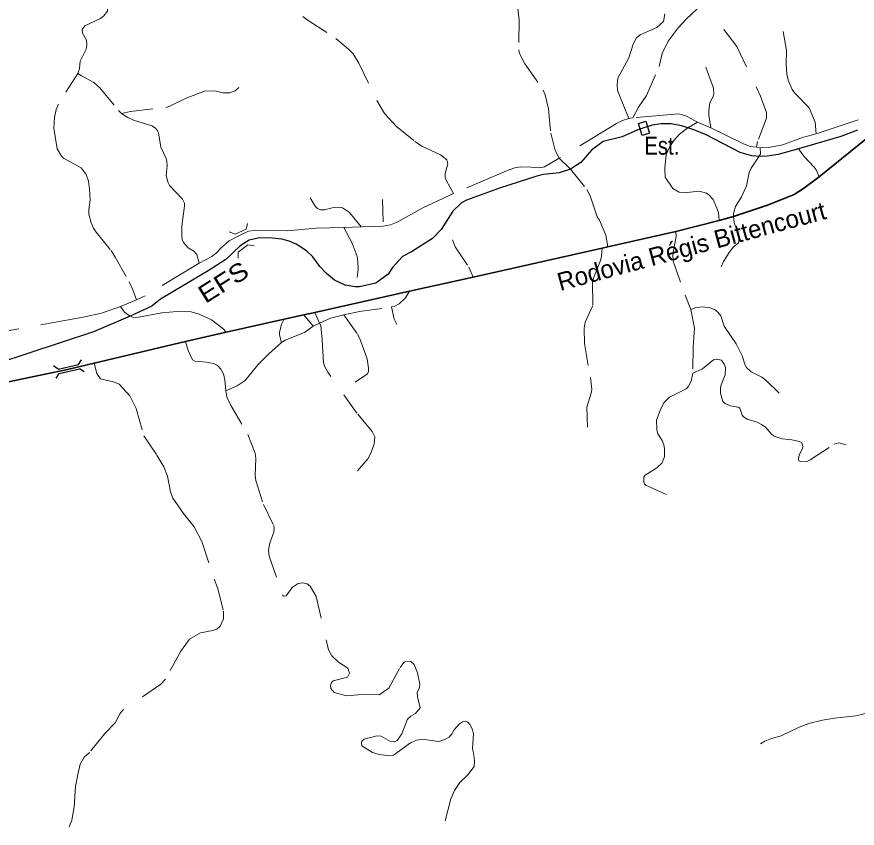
# Model space of a CAD drawing. Extents: x 220.8 to 246.7, y 7287.6 to 7315.8.
# Drawn here: x 239.405 to 243.157, y 7305.147 to 7308.771 of the extents above; entities that cross this region are included whole.
import ezdxf
from ezdxf.enums import TextEntityAlignment as Align

# ---------------------------------------------------------------- set-up
doc = ezdxf.new("R2010")
doc.units = 0
doc.header["$LTSCALE"] = 0.032
for name, pattern in [('DOTTED', [1.5, 0.3, -1.2]), ('LONG_DASHED', [7.5, 6, -1.5]), ('MEDIUM_DASHED', [4.5, 3, -1.5])]:
    doc.linetypes.add(name, pattern=pattern)
for name, color, linetype, lineweight in [('10', 7, 'Continuous', 25), ('11', 7, 'Continuous', 13), ('15', 7, 'Continuous', 25), ('2', 7, 'Continuous', 35), ('28', 7, 'Continuous', 25), ('5', 7, 'LONG_DASHED', 13), ('6', 7, 'MEDIUM_DASHED', 13), ('7', 7, 'DOTTED', 13)]:
    doc.layers.add(name, color=color, linetype=linetype, lineweight=lineweight)
doc.layers.add('61', color=7, linetype='Continuous')

msp = doc.modelspace()

# ---------------------------------------------------------------- linework, layer by layer
at = {"layer": '10'}
for p, q in [((239.5894, 7307.1977), (239.5686, 7307.2113)), ((239.5803, 7307.1573), (239.5937, 7307.1782)), ((239.5937, 7307.1782), (239.6841, 7307.1978)), ((239.7051, 7307.1844), (239.6841, 7307.1978))]:
    msp.add_line(p, q, dxfattribs=at)
msp.add_lwpolyline([(239.5894, 7307.1977), (239.6798, 7307.2174), (239.6934, 7307.2384)], dxfattribs=at)
at = {"layer": '11'}
for points in [[(240.4354, 7307.8477), (240.4286, 7307.8218), (240.3794, 7307.7994), (240.3534, 7307.8101)], [(240.3926, 7307.6931), (240.3936, 7307.7199), (240.4367, 7307.7525), (240.4644, 7307.7477)]]:
    msp.add_lwpolyline(points, dxfattribs=at)
at = {"layer": '15'}
for points in [[(243.1583, 7308.265), (243.0839, 7308.236), (242.8956, 7308.1818), (242.8045, 7308.1556), (242.7549, 7308.1479), (242.7241, 7308.1462), (242.6865, 7308.1497), (242.6344, 7308.1642), (242.4823, 7308.2437), (242.4327, 7308.265), (242.4016, 7308.2747), (242.3721, 7308.2838), (242.3259, 7308.2924), (242.2815, 7308.2924), (242.2422, 7308.2864), (242.1772, 7308.2667), (242.108, 7308.2343), (242.0234, 7308.2137), (241.9713, 7308.1753), (241.9226, 7308.1197), (241.8763, 7308.0903), (241.826, 7308.0736), (241.7568, 7308.0668), (241.726, 7308.0591), (241.5594, 7308.0052), (241.4132, 7307.9514), (241.3902, 7307.9394), (241.3517, 7307.9027), (241.2996, 7307.8206), (241.2611, 7307.7813), (241.1663, 7307.7215), (241.1261, 7307.7002), (241.0817, 7307.6506), (241.0629, 7307.6215), (241.0073, 7307.5814), (240.9355, 7307.5643), (240.915, 7307.5643), (240.8706, 7307.572), (240.8227, 7307.595), (240.7877, 7307.6241), (240.7578, 7307.6557), (240.7262, 7307.6993), (240.6988, 7307.7249), (240.6527, 7307.7548), (240.6211, 7307.7685), (240.5886, 7307.7779), (240.545, 7307.7822), (240.4878, 7307.783), (240.4425, 7307.7736), (240.4014, 7307.748)], [(240.4014, 7307.748), (240.3382, 7307.6873), (240.2587, 7307.6361), (240.0468, 7307.5096), (240.0075, 7307.4788), (239.9108, 7307.4345), (239.7468, 7307.3643), (239.3125, 7307.2206)]]:
    msp.add_lwpolyline(points, dxfattribs=at)
at = {"layer": '2'}
msp.add_lwpolyline([(239.3316, 7307.1323), (239.6303, 7307.1959), (239.7503, 7307.2242), (240.1574, 7307.3206), (240.3398, 7307.3618), (240.5989, 7307.4198), (240.6861, 7307.4393), (240.736, 7307.4505), (241.158, 7307.5449), (241.4416, 7307.6085), (242.0188, 7307.7379), (242.043, 7307.7433), (242.3478, 7307.8117), (242.5412, 7307.8613), (242.6047, 7307.8784), (242.757, 7307.9292), (242.8764, 7307.9777), (242.9171, 7308.004), (242.9873, 7308.0568), (243.1979, 7308.2257)], dxfattribs=at)
at = {"layer": '28'}
msp.add_lwpolyline([(242.2126, 7308.3047), (242.23, 7308.2504), (242.1977, 7308.2401), (242.1803, 7308.2944)], close=True, dxfattribs=at)
at = {"layer": '5'}
for points in [[(242.1368, 7308.3159), (242.0873, 7308.441), (242.0847, 7308.4687), (242.0886, 7308.4965), (242.1376, 7308.5877), (242.1561, 7308.6485), (242.1719, 7308.6776), (242.1878, 7308.6908), (242.2631, 7308.7238), (242.2916, 7308.7506), (242.2984, 7308.7836)], [(243.1608, 7308.311), (242.9743, 7308.2489), (242.9124, 7308.2325), (242.8258, 7308.1983), (242.7695, 7308.1883), (242.7246, 7308.1859), (242.7079, 7308.188), (242.679, 7308.1923), (242.6468, 7308.2054), (242.5037, 7308.2744), (242.4442, 7308.3006), (242.3951, 7308.3273), (242.3611, 7308.3371), (242.1548, 7308.3196), (242.1368, 7308.3159)], [(242.1368, 7308.3159), (242.1086, 7308.308), (242.0824, 7308.2939), (241.827, 7308.1399), (241.7615, 7308.1007), (241.7485, 7308.0977), (241.6529, 7308.1007), (241.6278, 7308.0967), (241.5905, 7308.0836), (241.3538, 7307.981), (241.2173, 7307.9177), (241.1037, 7307.8533), (241.0735, 7307.8412), (241.0404, 7307.8359), (240.9425, 7307.8327), (240.865, 7307.8302), (240.7395, 7307.8261), (240.6138, 7307.815), (240.4649, 7307.8171), (240.4397, 7307.813), (240.3923, 7307.7913), (240.3532, 7307.7708), (240.318, 7307.7406), (240.2949, 7307.7155), (240.2747, 7307.7004), (240.2184, 7307.6698), (239.978, 7307.5243), (239.9393, 7307.5065), (239.8673, 7307.477)], [(239.8673, 7307.477), (239.7828, 7307.4479), (239.7003, 7307.4298), (239.3631, 7307.368), (239.1492, 7307.3307), (239.0324, 7307.308), (238.8563, 7307.302), (238.8201, 7307.296), (238.789, 7307.2829), (238.7155, 7307.2296), (238.6854, 7307.218)], [(239.8673, 7307.477), (239.8857, 7307.4516), (239.9108, 7307.4345), (239.9221, 7307.4295), (239.9399, 7307.4273), (240.0521, 7307.4487), (240.1206, 7307.4552), (240.1827, 7307.453), (240.2192, 7307.443), (240.2734, 7307.418), (240.3241, 7307.3781), (240.3398, 7307.3618)]]:
    msp.add_lwpolyline(points, dxfattribs=at)
at = {"layer": '6'}
for points in [[(240.6812, 7308.7726), (240.7049, 7308.7547), (240.8284, 7308.6742), (240.8859, 7308.6268), (240.906, 7308.6053), (240.9311, 7308.5644), (241.0123, 7308.3977), (241.046, 7308.3389), (241.1006, 7308.2814), (241.1825, 7308.2139), (241.2155, 7308.1909), (241.296, 7308.155), (241.3254, 7308.132), (241.3297, 7308.1148), (241.3175, 7308.0703), (241.3175, 7308.0545), (241.3211, 7308.0415), (241.3538, 7307.981)], [(240.1574, 7307.3206), (240.1693, 7307.2801), (240.1897, 7307.2381), (240.1996, 7307.2325), (240.2496, 7307.2288), (240.283, 7307.222), (240.3009, 7307.2127), (240.3163, 7307.1973), (240.3268, 7307.1763), (240.3342, 7307.1497), (240.3373, 7307.0996), (240.3417, 7307.0737), (240.359, 7307.0373), (240.4362, 7306.9057), (240.4683, 7306.8216), (240.472, 7306.7975), (240.4695, 7306.7216), (240.472, 7306.6993), (240.506, 7306.5924), (240.5517, 7306.4991), (240.5542, 7306.4849), (240.553, 7306.4695), (240.5338, 7306.4213), (240.5289, 7306.3892), (240.5313, 7306.362), (240.5913, 7306.1896), (240.5956, 7306.1834), (240.6068, 7306.1846), (240.6339, 7306.2211), (240.6612, 7306.2397), (240.682, 7306.2426), (240.7006, 7306.2386), (240.7145, 7306.2275), (240.7414, 7306.1822), (240.797, 7305.9431), (240.8118, 7305.9171), (240.8409, 7305.8881), (240.8779, 7305.8646), (240.8841, 7305.8584), (240.8878, 7305.8485)], [(239.7503, 7307.2242), (239.7624, 7307.1773), (239.7779, 7307.1534), (239.8358, 7307.1405), (239.861, 7307.1302), (239.9093, 7307.078), (239.937, 7307.022), (239.9712, 7306.8989), (240.0304, 7306.8126), (240.0607, 7306.761), (240.0775, 7306.7185), (240.0904, 7306.6496), (240.102, 7306.6212), (240.149, 7306.5529), (240.196, 7306.4923), (240.2302, 7306.4266), (240.2856, 7306.2597), (240.3023, 7306.2179), (240.3275, 7306.1161)]]:
    msp.add_lwpolyline(points, dxfattribs=at)
at = {"layer": '7'}
for p, q in [((242.4031, 7308.2757), (242.4016, 7308.2747)), ((241.8759, 7308.0908), (241.8763, 7308.0903)), ((241.0381, 7307.9547), (241.0404, 7307.8359)), ((240.6861, 7307.4393), (240.7283, 7307.3895)), ((240.7564, 7307.403), (240.736, 7307.4505)), ((240.7283, 7307.3895), (240.7564, 7307.403))]:
    msp.add_line(p, q, dxfattribs=at)
for points in [[(242.1548, 7308.3196), (242.1803, 7308.3672), (242.2159, 7308.4198), (242.2723, 7308.5485), (242.2856, 7308.6064), (242.3127, 7308.6623), (242.3574, 7308.7213), (242.393, 7308.7606), (242.469, 7308.8308), (242.5333, 7308.8807), (242.57, 7308.9169), (242.5923, 7308.9499), (242.6099, 7308.9956), (242.6264, 7309.2369), (242.638, 7309.3268), (242.6423, 7309.4108), (242.6604, 7309.5554), (242.6673, 7309.6442), (242.6444, 7309.7329), (242.6269, 7309.8993), (242.6173, 7309.9445)], [(241.7065, 7309.2353), (241.6979, 7309.2171), (241.681, 7309.1595), (241.6666, 7309.1263), (241.629, 7308.9264), (241.6284, 7308.8775), (241.6415, 7308.8092), (241.6478, 7308.7565), (241.6459, 7308.6237), (241.6478, 7308.6105), (241.6735, 7308.5604), (241.7549, 7308.4432), (241.7637, 7308.4225), (241.7781, 7308.3605), (241.7888, 7308.2508), (241.807, 7308.1794), (241.8139, 7308.1612), (241.827, 7308.1399), (241.8763, 7308.0903)], [(239.8314, 7309.2094), (239.8358, 7309.1781), (239.8349, 7309.1382), (239.8036, 7309.0763), (239.8004, 7309.053), (239.8077, 7309.0259), (239.8211, 7308.999), (239.825, 7308.9802), (239.8234, 7308.9525), (239.8141, 7308.9148), (239.809, 7308.8775), (239.8103, 7308.7954), (239.7934, 7308.7753), (239.7777, 7308.7638), (239.7078, 7308.7306), (239.696, 7308.7137), (239.698, 7308.6984), (239.7158, 7308.6665), (239.7177, 7308.6445), (239.7139, 7308.6269), (239.6877, 7308.5723), (239.6849, 7308.5398), (239.6775, 7308.5181)], [(242.5617, 7308.7139), (242.6191, 7308.6382), (242.7254, 7308.4158), (242.7514, 7308.3435), (242.7522, 7308.3184), (242.7122, 7308.2142), (242.7079, 7308.188)], [(242.8268, 7308.7048), (242.8417, 7308.621), (242.8406, 7308.5608), (242.8434, 7308.5147), (242.8489, 7308.4877), (242.8669, 7308.4465), (242.8791, 7308.4303), (242.9421, 7308.3648), (242.9698, 7308.3008), (242.9743, 7308.2489)], [(242.5037, 7308.2744), (242.4945, 7308.3308), (242.4945, 7308.3521), (242.4995, 7308.3864), (242.5125, 7308.4113), (242.5167, 7308.426), (242.5161, 7308.4518), (242.4638, 7308.5918)], [(239.6775, 7308.5181), (239.5907, 7308.3812), (239.5799, 7308.3563), (239.5735, 7308.3218), (239.5706, 7308.2733), (239.5843, 7308.1814), (239.6044, 7308.1485), (239.6137, 7308.1396), (239.6916, 7308.0968), (239.7145, 7308.0665), (239.7248, 7308.0368), (239.7295, 7308.0011), (239.7324, 7307.9535), (239.726, 7307.9091), (239.7267, 7307.89), (239.7366, 7307.851), (239.7471, 7307.8262), (239.7583, 7307.8096), (239.8256, 7307.7266), (239.8435, 7307.6972), (239.906, 7307.5877), (239.9233, 7307.551), (239.9393, 7307.5065)], [(239.6775, 7308.5181), (239.6928, 7308.5066), (239.7479, 7308.4769), (239.7753, 7308.4534), (239.8593, 7308.3522), (239.8728, 7308.3397)], [(239.8728, 7308.3397), (239.9129, 7308.3481), (240.0702, 7308.3659), (240.0915, 7308.3732), (240.1612, 7308.4081), (240.2421, 7308.4387), (240.2889, 7308.4408), (240.3258, 7308.4311), (240.3561, 7308.4307), (240.3799, 7308.4398), (240.3956, 7308.4558)], [(239.8728, 7308.3397), (239.9004, 7308.3209), (239.9258, 7308.3096), (240.0075, 7308.2834), (240.0236, 7308.2728), (240.0333, 7308.2615), (240.0372, 7308.2529), (240.0478, 7308.1879), (240.0709, 7308.1387), (240.0744, 7308.125), (240.0763, 7308.1066), (240.072, 7308.0616), (240.0803, 7308.0292), (240.0865, 7308.0171), (240.144, 7307.9557), (240.153, 7307.9389), (240.1538, 7307.9264), (240.142, 7307.8364), (240.1409, 7307.7926), (240.1436, 7307.7758), (240.1495, 7307.7633), (240.1698, 7307.7394), (240.1956, 7307.7238), (240.2085, 7307.7093), (240.2184, 7307.6698)], [(242.4442, 7308.3006), (242.4016, 7308.2747), (242.3642, 7308.2468), (242.3378, 7308.218), (242.3208, 7308.1915), (242.3043, 7308.1561), (242.2977, 7308.0952), (242.2991, 7308.0551), (242.3335, 7308.0046), (242.3628, 7307.9872), (242.3845, 7307.9843), (242.452, 7307.9914), (242.4846, 7307.9829), (242.495, 7307.9763), (242.5143, 7307.9546), (242.5304, 7307.9164), (242.5379, 7307.897), (242.5412, 7307.8613)], [(242.7246, 7308.1859), (242.725, 7308.1582), (242.7171, 7308.1438), (242.6838, 7308.0942), (242.6754, 7308.0759), (242.6634, 7308.016), (242.6405, 7307.9661), (242.6143, 7307.9236), (242.6051, 7307.8928), (242.6047, 7307.8784), (242.6076, 7307.8516), (242.6188, 7307.8225), (242.628, 7307.7859), (242.6284, 7307.765), (242.6259, 7307.7592), (242.6047, 7307.743), (242.5855, 7307.7184), (242.5606, 7307.6785), (242.5493, 7307.6539)], [(242.8948, 7308.1833), (242.8956, 7308.1818), (242.9193, 7308.1483), (242.9651, 7308.0992), (242.9738, 7308.0872), (242.9873, 7308.0568)], [(241.8763, 7308.0903), (241.9499, 7307.999), (241.965, 7307.9717), (241.9966, 7307.8775), (242.0067, 7307.8631), (242.034, 7307.7961), (242.043, 7307.7433)], [(240.7147, 7307.963), (240.7375, 7307.9245), (240.7477, 7307.9148), (240.7607, 7307.9092), (240.7783, 7307.9088), (240.8126, 7307.9176), (240.8516, 7307.9194), (240.8595, 7307.9171), (240.8901, 7307.8967), (240.9425, 7307.8327)], [(240.9249, 7307.6058), (240.9281, 7307.6425), (240.9277, 7307.6764), (240.924, 7307.7), (240.9026, 7307.7599), (240.865, 7307.8302)], [(242.3478, 7307.8117), (242.3487, 7307.7892), (242.3334, 7307.7102), (242.335, 7307.6794), (242.3884, 7307.5282), (242.4147, 7307.4631)], [(241.3499, 7307.7748), (241.3619, 7307.7438), (241.4233, 7307.6525), (241.4416, 7307.6085)], [(242.0188, 7307.7379), (242.0157, 7307.7021), (242.0108, 7307.6831), (241.9796, 7307.6034), (241.9754, 7307.5838), (241.9761, 7307.4817), (241.9431, 7307.4069), (241.9385, 7307.3795), (241.9389, 7307.3114), (241.9659, 7307.1598), (241.9715, 7307.1061), (241.9691, 7307.0893), (241.9501, 7307.0279), (241.9526, 7306.9377)], [(241.0776, 7307.4747), (241.089, 7307.4767), (241.1112, 7307.4889), (241.1402, 7307.5157), (241.158, 7307.5449)], [(240.8652, 7307.4391), (240.9354, 7307.4549), (241.0776, 7307.4747)], [(241.0776, 7307.4747), (241.0901, 7307.4209), (241.1016, 7307.3962)], [(242.4147, 7307.4631), (242.4328, 7307.4708), (242.4651, 7307.4749), (242.5009, 7307.4703), (242.5194, 7307.4631), (242.5348, 7307.4519), (242.5476, 7307.4355), (242.5629, 7307.3894), (242.6172, 7307.3095), (242.6434, 7307.2572), (242.6562, 7307.2152), (242.6633, 7307.2049), (242.6833, 7307.185), (242.731, 7307.1614), (242.7494, 7307.1481), (242.8093, 7307.0902)], [(240.7564, 7307.403), (240.8058, 7307.4244), (240.8652, 7307.4391)], [(240.8652, 7307.4391), (240.9254, 7307.355), (240.939, 7307.3256), (240.9684, 7307.2426), (240.9745, 7307.2014), (240.9748, 7307.1867), (240.9712, 7307.1756), (240.915, 7307.1384)], [(242.4147, 7307.4631), (242.4313, 7307.3802), (242.4241, 7307.2968), (242.4229, 7307.1793)], [(240.5869, 7307.3164), (240.5774, 7307.3498), (240.5777, 7307.362), (240.5865, 7307.3966), (240.5989, 7307.4198)], [(240.9254, 7306.7427), (240.9723, 7306.7972), (240.9841, 7306.8194), (241.0002, 7306.8616), (241.0031, 7306.8949), (240.9917, 7306.9193), (240.9226, 7307.0009), (240.7937, 7307.1838), (240.779, 7307.2107), (240.7747, 7307.2272), (240.7686, 7307.3278), (240.7614, 7307.3915), (240.7564, 7307.403)], [(240.5869, 7307.3164), (240.6032, 7307.326), (240.6888, 7307.3614), (240.7283, 7307.3895)], [(240.3373, 7307.0996), (240.388, 7307.1219), (240.4238, 7307.1462), (240.4815, 7307.2161), (240.5294, 7307.2658), (240.5869, 7307.3164)], [(242.4229, 7307.1793), (242.4661, 7307.1983), (242.5158, 7307.2388), (242.5276, 7307.2418), (242.5506, 7307.2372), (242.5634, 7307.2198), (242.5696, 7307.2039), (242.5675, 7307.1722), (242.5491, 7307.1271), (242.5471, 7307.1143), (242.5465, 7307.0897), (242.5578, 7307.0533), (242.5675, 7307.0436), (242.5906, 7307.0333), (242.6249, 7307.0272), (242.6331, 7307.0226), (242.6428, 7306.9923), (242.65, 7306.9847), (242.6659, 7306.9744), (242.711, 7306.9596), (242.7294, 7306.9503), (242.7494, 7306.9365), (242.7755, 7306.9047), (242.7863, 7306.8971), (242.8222, 7306.8853), (242.8657, 7306.8807), (242.9, 7306.8735), (242.9098, 7306.8679), (242.9144, 7306.852), (242.9123, 7306.8422), (242.898, 7306.8151), (242.8954, 7306.7946), (242.8969, 7306.7879), (242.9021, 7306.7844), (242.9297, 7306.7838), (242.9477, 7306.7926), (243.0537, 7306.8622), (243.0757, 7306.8679), (243.1075, 7306.8597)], [(242.4229, 7307.1793), (242.4165, 7307.1436), (242.402, 7307.1179), (242.3932, 7307.1095), (242.3194, 7307.0718), (242.2937, 7307.0461), (242.2769, 7307.0128), (242.2617, 7306.9699), (242.2621, 7306.9282), (242.2673, 7306.9078), (242.2857, 7306.8781), (242.2941, 7306.8584), (242.2973, 7306.8432), (242.2961, 7306.8051), (242.2841, 7306.7778), (242.2629, 7306.757), (242.2111, 7306.7229), (242.2051, 7306.7141), (242.2051, 7306.6944), (242.2079, 7306.6852), (242.2139, 7306.6788), (242.3122, 7306.6339)], [(240.3275, 7306.1161), (240.3268, 7306.0813), (240.312, 7306.049), (240.2972, 7306.0362), (240.2792, 7306.0291), (240.225, 7306.0188), (240.1754, 7305.9904), (240.1368, 7305.9382), (240.0678, 7305.8119), (240.0478, 7305.7907), (239.8797, 7305.6753), (239.8642, 7305.6579), (239.8436, 7305.6173), (239.7978, 7305.5697), (239.7289, 7305.4846), (239.7057, 7305.464), (239.687, 7305.4324), (239.6767, 7305.3873), (239.667, 7305.3332), (239.6606, 7305.2417), (239.6554, 7305.2076), (239.6503, 7305.1831), (239.6387, 7305.1521)], [(240.8878, 7305.8485), (240.89, 7305.8387), (240.881, 7305.822), (240.8174, 7305.8047), (240.8094, 7305.7973), (240.8057, 7305.7843), (240.8075, 7305.7701), (240.8211, 7305.7534), (240.8767, 7305.738), (240.9465, 7305.7438), (241.0219, 7305.7417), (241.0658, 7305.7719), (241.1164, 7305.8652), (241.1342, 7305.8881), (241.144, 7305.8928), (241.1637, 7305.8907), (241.1783, 7305.8778), (241.1933, 7305.8414), (241.2037, 7305.7906), (241.2027, 7305.7755), (241.1928, 7305.7527), (241.1933, 7305.7335), (241.2058, 7305.6844), (241.185, 7305.659), (241.1646, 7305.6475), (241.1495, 7305.6343), (241.1231, 7305.5687), (241.103, 7305.539), (241.0898, 7305.5322), (241.0726, 7305.5347), (241.0314, 7305.5573), (241.0128, 7305.5594), (240.9562, 7305.5451), (240.9458, 7305.5351), (240.943, 7305.5279), (240.9458, 7305.5147), (240.9927, 7305.485), (241.0228, 7305.4757), (241.0579, 7305.471), (241.0865, 7305.4724), (241.1628, 7305.5279), (241.1896, 7305.5401), (241.2101, 7305.5433), (241.2358, 7305.5419), (241.2888, 7305.5337), (241.3182, 7305.544), (241.3346, 7305.5537), (241.3468, 7305.568), (241.3561, 7305.5852), (241.3812, 7305.6124), (241.3948, 7305.6221), (241.4084, 7305.6246), (241.4191, 7305.6199), (241.4295, 7305.6085), (241.4392, 7305.5866), (241.4435, 7305.5684), (241.4399, 7305.5014), (241.4431, 7305.4835), (241.4478, 7305.4477), (241.4474, 7305.4227), (241.4181, 7305.3847), (241.3823, 7305.3507), (241.3594, 7305.3145), (241.3422, 7305.2773), (241.3021, 7305.1173)], [(242.7254, 7305.5233), (242.745, 7305.5356), (242.7749, 7305.5478), (242.8181, 7305.5587), (242.8984, 7305.5978), (242.9407, 7305.6146), (243.0024, 7305.6296), (243.0551, 7305.6382), (243.1504, 7305.6482), (243.1781, 7305.6541), (243.2226, 7305.67), (243.2939, 7305.6991), (243.3502, 7305.7354), (243.3852, 7305.7522), (243.439, 7305.7847)]]:
    msp.add_lwpolyline(points, dxfattribs=at)

# ---------------------------------------------------------------- texts
at = {"layer": '61', "width": 0.85}
msp.add_text('Est.', height=0.08, dxfattribs=at).set_placement((242.2064, 7308.1551))
at = {"layer": '61'}
msp.add_text('Rodovia Régis Bittencourt', height=0.08, rotation=15.174, dxfattribs=at).set_placement((242.4277, 7307.7077), align=Align.CENTER)
at = {"layer": '61', "width": 1.15}
msp.add_text('EFS', height=0.08, rotation=32.276, dxfattribs=at).set_placement((240.3481, 7307.552), align=Align.CENTER)

doc.saveas('drawing.dxf')
